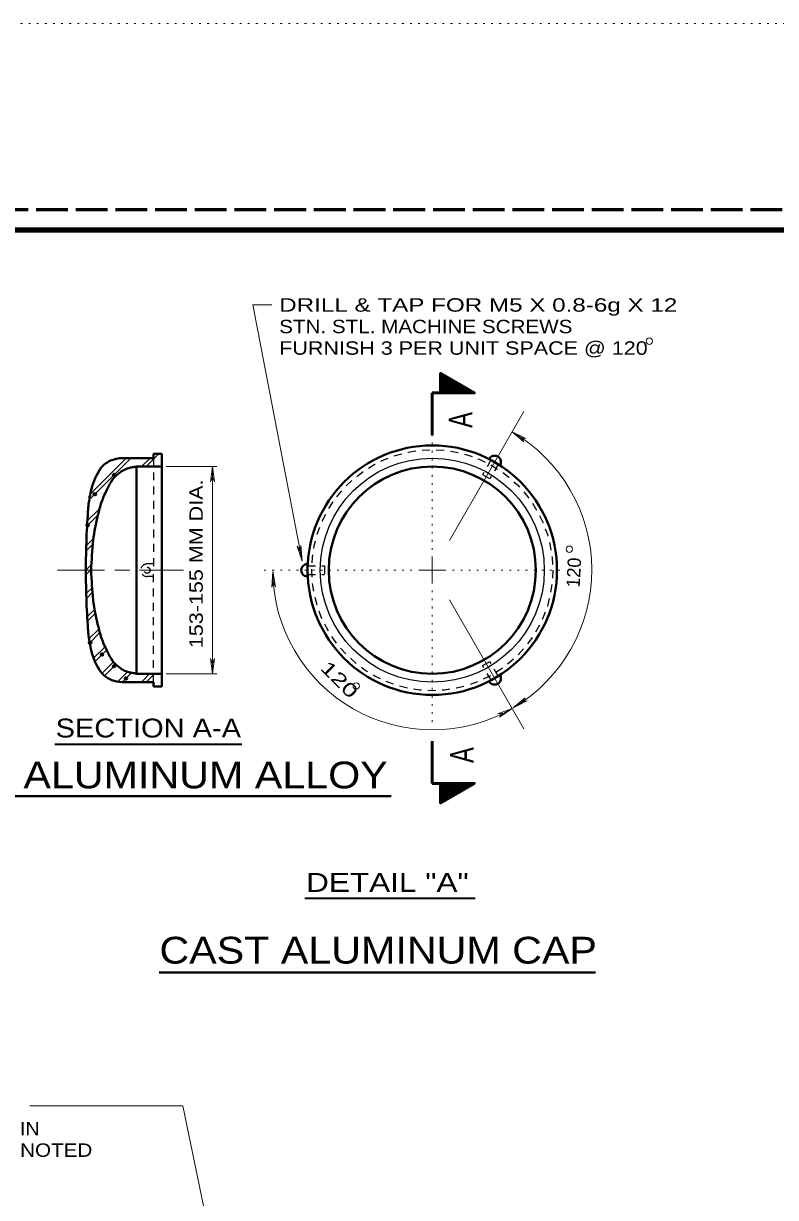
# Model space of a CAD drawing. Extents: x 312583 to 312854, y 144419 to 144597.
# Drawn here: x 312680.5 to 312723.1, y 144530.3 to 144596.8 of the extents above; entities that cross this region are included whole.
import ezdxf
from ezdxf.enums import TextEntityAlignment as Align

# ---------------------------------------------------------------- set-up
doc = ezdxf.new("R2010")
doc.units = 0
doc.header["$LTSCALE"] = 0.3
doc.header["$PDMODE"] = 32
doc.header["$PDSIZE"] = 0.15
for name, pattern in [('DOTTED', [1.5, 0.3, -1.2]), ('LONG_DASHED', [7.5, 6, -1.5]), ('SHORT_DASHED', [2.7, 1.5, -1.2])]:
    doc.linetypes.add(name, pattern=pattern)
for name, color, linetype, lineweight in [('1', 7, 'Continuous', 35), ('2', 7, 'Continuous', 13), ('62', 7, 'DOTTED', 13), ('63', 7, 'LONG_DASHED', 60)]:
    doc.layers.add(name, color=color, linetype=linetype, lineweight=lineweight)

msp = doc.modelspace()

# ---------------------------------------------------------------- linework, layer by layer
at = {"layer": '1', "lineweight": 13}
for p, q in [((312708.8486, 144574.7913), (312704.6319, 144567.485)), ((312684.2616, 144569.8463), (312686.5693, 144572.1616)), ((312684.2999, 144570.1606), (312686.2626, 144572.1233)), ((312687.1749, 144571.6786), (312687.6579, 144572.1616)), ((312687.4433, 144571.6786), (312688.1639, 144572.3993)), ((312687.8496, 144572.3533), (312687.8956, 144572.3993)), ((312684.0853, 144568.3206), (312684.7139, 144568.9493)), ((312684.0929, 144568.6043), (312684.7829, 144569.2866)), ((312684.0546, 144567.209), (312684.4379, 144567.5846)), ((312684.0469, 144566.9253), (312684.3919, 144567.2703)), ((312684.0163, 144565.8136), (312684.3306, 144566.128)), ((312684.0239, 144565.5453), (312684.3153, 144565.8443)), ((312684.0393, 144564.4796), (312684.3766, 144564.817)), ((312684.0469, 144564.2113), (312684.3996, 144564.564)), ((312708.8486, 144556.8283), (312704.6319, 144564.1346)), ((312684.0699, 144563.1533), (312684.5376, 144563.621)), ((312684.0853, 144562.8926), (312684.5759, 144563.391)), ((312684.1926, 144561.919), (312684.7293, 144562.4556)), ((312684.2156, 144561.6736), (312684.7983, 144562.2563)), ((312684.5069, 144560.884), (312685.1049, 144561.4743)), ((312684.5989, 144560.7), (312685.1816, 144561.2826)), ((312684.9516, 144559.9716), (312685.6109, 144560.631)), ((312685.0743, 144559.8183), (312685.7489, 144560.5006)), ((312685.8486, 144559.5116), (312686.4159, 144560.079)), ((312686.1093, 144559.504), (312686.6306, 144560.0176)), ((312687.1673, 144559.4733), (312687.6349, 144559.941)), ((312687.4356, 144559.4733), (312687.9033, 144559.941)), ((312688.2713, 144559.2203), (312688.3249, 144559.2816))]:
    msp.add_line(p, q, dxfattribs=at)
at = {"layer": '1', "lineweight": 40}
for p, q in [((312687.8496, 144572.1616), (312686.4083, 144572.1616)), ((312687.8496, 144572.1616), (312687.8496, 144572.3993)), ((312706.8859, 144572.108), (312707.5069, 144571.7553)), ((312686.8913, 144571.6786), (312686.8913, 144565.8136)), ((312688.3249, 144571.6786), (312688.3249, 144565.8136)), ((312696.5896, 144565.4533), (312696.5896, 144566.1663)), ((312686.8913, 144559.941), (312686.8913, 144565.8136)), ((312688.3249, 144559.941), (312688.3249, 144565.8136)), ((312687.8496, 144559.458), (312686.4083, 144559.458)), ((312687.8496, 144559.458), (312687.8496, 144559.2203)), ((312707.5069, 144559.872), (312706.8859, 144559.5116))]:
    msp.add_line(p, q, dxfattribs=at)
at = {"layer": '1', "linetype": 'SHORT_DASHED', "lineweight": 25}
for p, q in [((312687.8496, 144572.1616), (312687.8496, 144565.8136)), ((312706.9856, 144572.0543), (312706.5103, 144571.2186)), ((312707.3996, 144571.8166), (312706.9243, 144570.981)), ((312706.9243, 144570.981), (312706.5103, 144571.2186)), ((312687.8496, 144566.1663), (312687.4893, 144566.1663)), ((312687.8496, 144565.4533), (312687.4893, 144565.4533)), ((312687.8496, 144559.458), (312687.8496, 144565.8136)), ((312696.5896, 144566.0513), (312697.5479, 144566.0513)), ((312696.5896, 144565.5683), (312697.5479, 144565.5683)), ((312697.5479, 144566.0513), (312697.5479, 144565.5683)), ((312706.5103, 144560.401), (312706.9243, 144560.6386)), ((312706.9933, 144559.573), (312706.5103, 144560.401)), ((312707.3996, 144559.8106), (312706.9243, 144560.6386))]:
    msp.add_line(p, q, dxfattribs=at)
at = {"layer": '1', "lineweight": 158}
msp.add_lwpolyline([(312616.5, 144423.1446), (312616.5, 144585.0846), (312849, 144585.0846)], dxfattribs=at)
at = {"layer": '1', "lineweight": 40}
for points in [[(312686.8913, 144571.6786), (312688.3249, 144571.6786), (312688.3249, 144572.3993), (312687.8496, 144572.3993)], [(312686.8913, 144559.941), (312688.3249, 144559.941), (312688.3249, 144559.2203), (312687.8496, 144559.2203)]]:
    msp.add_lwpolyline(points, dxfattribs=at)
for radius in [7.0687, 5.8708]:
    msp.add_circle((312703.6602, 144565.8098), radius, dxfattribs=at)
at = {"layer": '1', "linetype": 'SHORT_DASHED', "lineweight": 25}
for centre, radius in [((312703.6602, 144565.8098), 6.8291), ((312687.4912, 144565.8079), 0.17)]:
    msp.add_circle(centre, radius, dxfattribs=at)
at = {"layer": '1', "lineweight": 25}
msp.add_circle((312703.6602, 144565.8098), 6.3499, dxfattribs=at)
at = {"layer": '1', "lineweight": 40}
for centre, start, end in [((312707.1952, 144571.9345), 329.52448, 150.47552), ((312696.5885, 144565.8088), 89.52448, 270.47552), ((312707.1968, 144559.6861), 209.52448, 30.47552)]:
    msp.add_arc(centre, 0.3575, start, end, dxfattribs=at)
at = {"layer": '1', "linetype": 'SHORT_DASHED', "lineweight": 25}
msp.add_arc((312687.4921, 144565.8069), 0.3575, 90.15361, 269.84639, dxfattribs=at)
at = {"layer": '1', "lineweight": 40}
for points in [[(312684.0163, 144565.8136), (312684.0393, 144567.1706), (312684.1236, 144568.9263), (312684.2003, 144569.7466), (312684.3843, 144570.5746), (312684.6219, 144571.1726), (312684.9439, 144571.6786), (312685.4959, 144572.0466), (312685.7566, 144572.1233), (312686.4083, 144572.1616)], [(312686.8913, 144571.6786), (312686.6613, 144571.6403), (312686.4466, 144571.5943), (312686.1246, 144571.464), (312685.8333, 144571.257), (312685.4499, 144570.82), (312685.2046, 144570.36), (312684.9056, 144569.6623), (312684.7063, 144568.934), (312684.5453, 144568.221), (312684.4379, 144567.508), (312684.3153, 144565.7983)], [(312684.0163, 144565.8136), (312684.0393, 144564.449), (312684.1236, 144562.6933), (312684.2003, 144561.8806), (312684.3843, 144561.045), (312684.6219, 144560.447), (312684.9439, 144559.9486), (312685.4959, 144559.5806), (312685.7566, 144559.504), (312686.4083, 144559.458)], [(312686.8913, 144559.941), (312686.6613, 144559.987), (312686.4466, 144560.0253), (312686.1246, 144560.1556), (312685.8333, 144560.3626), (312685.4499, 144560.7996), (312685.2046, 144561.2596), (312684.9056, 144561.9573), (312684.7063, 144562.6856), (312684.5453, 144563.3986), (312684.4379, 144564.1193), (312684.3153, 144565.7983)]]:
    msp.add_spline(points, degree=3, dxfattribs=at)
at = {"layer": '1'}
for p in [(312685.6109, 144571.2033), (312684.5299, 144570.1146), (312684.1236, 144568.359), (312684.2616, 144561.712), (312684.9363, 144561.0373), (312685.6109, 144560.3626), (312686.2933, 144559.6803)]:
    msp.add_point(p, dxfattribs=at)
at = {"layer": '2'}
for p, q in [((312694.5579, 144580.8403), (312693.4923, 144580.8403)), ((312696.2753, 144566.3273), (312693.4923, 144580.8403)), ((312708.1816, 144573.6413), (312708.8563, 144573.0816)), ((312708.1816, 144573.6413), (312708.9713, 144573.2656)), ((312708.8563, 144573.0816), (312708.6799, 144573.327)), ((312708.9713, 144573.2656), (312708.6799, 144573.327)), ((312688.5703, 144571.6786), (312691.4453, 144571.6786)), ((312691.1999, 144571.6786), (312691.0926, 144570.8123)), ((312691.1999, 144559.941), (312691.1999, 144571.6786)), ((312691.1999, 144571.6786), (312691.3073, 144570.8123)), ((312691.0926, 144570.8123), (312691.1999, 144571.0883)), ((312691.3073, 144570.8123), (312691.1999, 144571.0883)), ((312696.0069, 144567.163), (312696.1603, 144566.91)), ((312696.2753, 144566.3273), (312696.0069, 144567.163)), ((312696.2139, 144567.2013), (312696.1603, 144566.91)), ((312696.2753, 144566.3273), (312696.2139, 144567.2013)), ((312703.6583, 144565.8136), (312703.6583, 144566.5803)), ((312682.4139, 144565.8136), (312685.0666, 144565.8136)), ((312685.6569, 144565.8136), (312686.5079, 144565.8136)), ((312687.0676, 144565.8136), (312689.5516, 144565.8136)), ((312694.6193, 144565.7293), (312694.5656, 144564.8553)), ((312694.6193, 144565.7293), (312694.7726, 144564.8706)), ((312703.6583, 144565.8136), (312702.8916, 144565.8136)), ((312703.6583, 144565.8136), (312702.8916, 144565.8136)), ((312703.6583, 144565.8136), (312703.6583, 144565.047)), ((312703.6583, 144565.8136), (312704.4249, 144565.8136)), ((312694.5656, 144564.8553), (312694.6499, 144565.139)), ((312694.7726, 144564.8706), (312694.6499, 144565.139)), ((312691.0926, 144560.8073), (312691.1999, 144560.5313)), ((312691.1999, 144559.941), (312691.0926, 144560.8073)), ((312691.3073, 144560.8073), (312691.1999, 144560.5313)), ((312691.1999, 144559.941), (312691.3073, 144560.8073)), ((312688.5703, 144559.941), (312691.4453, 144559.941)), ((312708.2506, 144558.0166), (312708.9176, 144558.584)), ((312708.2506, 144558.0166), (312709.0326, 144558.4076)), ((312708.9176, 144558.584), (312708.7489, 144558.3463)), ((312709.0326, 144558.4076), (312708.7489, 144558.3463)), ((312708.1816, 144557.9783), (312707.3613, 144557.6716)), ((312707.3613, 144557.6716), (312707.6603, 144557.71)), ((312708.1816, 144557.9783), (312707.4609, 144557.4876)), ((312707.4609, 144557.4876), (312707.6603, 144557.71))]:
    msp.add_line(p, q, dxfattribs=at)
at = {"layer": '2', "lineweight": 35}
for p, q in [((312704.1336, 144576.938), (312704.1489, 144576.9533)), ((312704.1336, 144576.892), (312704.1719, 144576.9456)), ((312704.1336, 144576.8383), (312704.1873, 144576.9303)), ((312704.1336, 144576.7923), (312704.2103, 144576.915)), ((312704.1336, 144576.7386), (312704.2333, 144576.9073)), ((312704.1336, 144576.7003), (312704.2486, 144576.892)), ((312704.1336, 144576.6466), (312704.2716, 144576.8843)), ((312704.1336, 144576.6006), (312704.2946, 144576.869)), ((312704.1336, 144576.5546), (312704.3099, 144576.8613)), ((312704.1336, 144576.5086), (312704.3406, 144576.846)), ((312704.1336, 144576.455), (312704.3559, 144576.8383)), ((312704.1336, 144576.409), (312704.3789, 144576.823)), ((312704.1336, 144576.363), (312704.4019, 144576.8153)), ((312704.1336, 144576.3093), (312704.4173, 144576.8)), ((312704.1336, 144576.2633), (312704.4403, 144576.7923)), ((312704.1336, 144576.2173), (312704.4556, 144576.777)), ((312704.1336, 144576.1636), (312704.4786, 144576.7616)), ((312704.1336, 144576.1176), (312704.5016, 144576.754)), ((312704.1336, 144576.0716), (312704.5169, 144576.7386)), ((312704.1336, 144576.0256), (312704.5399, 144576.7233)), ((312704.1336, 144575.972), (312704.5629, 144576.7156)), ((312704.1336, 144575.9336), (312704.5783, 144576.7003)), ((312704.1336, 144575.88), (312704.6089, 144576.6926)), ((312704.1489, 144575.857), (312704.6243, 144576.6773)), ((312704.1796, 144575.857), (312704.6473, 144576.6696)), ((312704.2103, 144575.857), (312704.6703, 144576.6543)), ((312704.2333, 144575.857), (312704.6856, 144576.6466)), ((312704.2639, 144575.857), (312704.7086, 144576.6313)), ((312704.2869, 144575.8646), (312704.7316, 144576.6236)), ((312704.3176, 144575.8646), (312704.7469, 144576.6083)), ((312704.3406, 144575.857), (312704.7699, 144576.6006)), ((312704.3713, 144575.857), (312704.7929, 144576.5853)), ((312704.4019, 144575.857), (312704.8083, 144576.57)), ((312704.4249, 144575.857), (312704.8313, 144576.5623)), ((312704.4556, 144575.857), (312704.8543, 144576.547)), ((312704.4863, 144575.857), (312704.8773, 144576.5316)), ((312704.5093, 144575.857), (312704.8926, 144576.524)), ((312704.5399, 144575.8646), (312704.9156, 144576.5086)), ((312704.5706, 144575.857), (312704.9386, 144576.501)), ((312704.5936, 144575.857), (312704.9539, 144576.4856)), ((312704.6166, 144575.857), (312704.9769, 144576.478)), ((312704.6473, 144575.857), (312704.9999, 144576.4626)), ((312704.6779, 144575.857), (312705.0153, 144576.455)), ((312704.7086, 144575.857), (312705.0383, 144576.4396)), ((312704.7316, 144575.857), (312705.0613, 144576.432)), ((312704.7623, 144575.857), (312705.0766, 144576.4166)), ((312704.7853, 144575.8646), (312705.1073, 144576.409)), ((312704.8159, 144575.857), (312705.1226, 144576.3936)), ((312704.8389, 144575.857), (312705.1456, 144576.3783)), ((312704.8696, 144575.857), (312705.1686, 144576.3706)), ((312704.9003, 144575.857), (312705.1839, 144576.3553)), ((312704.9233, 144575.857), (312705.2069, 144576.3476)), ((312704.9539, 144575.857), (312705.2299, 144576.3323)), ((312704.9846, 144575.857), (312705.2453, 144576.3246)), ((312705.0076, 144575.857), (312705.2683, 144576.3093)), ((312705.0383, 144575.857), (312705.2913, 144576.3016)), ((312705.0689, 144575.857), (312705.3066, 144576.2863)), ((312705.0919, 144575.857), (312705.3296, 144576.2786)), ((312705.1149, 144575.857), (312705.3526, 144576.2633)), ((312705.1456, 144575.857), (312705.3756, 144576.2556)), ((312705.1763, 144575.857), (312705.3909, 144576.2403)), ((312705.2069, 144575.857), (312705.4139, 144576.225)), ((312705.2299, 144575.857), (312705.4369, 144576.2173)), ((312705.2606, 144575.857), (312705.4523, 144576.202)), ((312705.2836, 144575.857), (312705.4753, 144576.1866)), ((312705.3143, 144575.857), (312705.4983, 144576.179)), ((312705.3373, 144575.857), (312705.5136, 144576.1636)), ((312705.3679, 144575.857), (312705.5366, 144576.156)), ((312705.3986, 144575.857), (312705.5596, 144576.1406)), ((312705.4216, 144575.857), (312705.5749, 144576.133)), ((312705.4523, 144575.857), (312705.6056, 144576.1176)), ((312705.4753, 144575.857), (312705.6209, 144576.11)), ((312705.5059, 144575.857), (312705.6439, 144576.0946)), ((312705.5366, 144575.857), (312705.6669, 144576.087)), ((312705.5596, 144575.857), (312705.6823, 144576.0716)), ((312705.5903, 144575.857), (312705.7053, 144576.064)), ((312705.6133, 144575.857), (312705.7283, 144576.0486)), ((312705.6439, 144575.857), (312705.7436, 144576.0333)), ((312705.6746, 144575.857), (312705.7666, 144576.0256)), ((312705.7053, 144575.857), (312705.7896, 144576.0103)), ((312705.7283, 144575.857), (312705.8049, 144575.995)), ((312705.7589, 144575.857), (312705.8279, 144575.9873)), ((312705.7819, 144575.857), (312705.8509, 144575.972)), ((312705.8049, 144575.857), (312705.8739, 144575.9643)), ((312705.8356, 144575.857), (312705.8893, 144575.949)), ((312705.8663, 144575.857), (312705.9123, 144575.9413)), ((312705.8969, 144575.857), (312705.9353, 144575.926)), ((312705.9199, 144575.857), (312705.9506, 144575.9183)), ((312705.9506, 144575.857), (312705.9736, 144575.903)), ((312705.9736, 144575.857), (312705.9966, 144575.8953)), ((312706.0043, 144575.857), (312706.0119, 144575.88)), ((312706.0349, 144575.857), (312706.0349, 144575.8723)), ((312682.2567, 144555.948), (312692.8636, 144555.948)), ((312704.1336, 144553.7003), (312704.6089, 144552.8876)), ((312704.1336, 144553.6466), (312704.5783, 144552.88)), ((312704.1336, 144553.6083), (312704.5629, 144552.8646)), ((312704.1336, 144553.5546), (312704.5399, 144552.857)), ((312704.1336, 144553.5086), (312704.5169, 144552.8416)), ((312704.1489, 144553.7233), (312704.6243, 144552.903)), ((312704.1796, 144553.7233), (312704.6473, 144552.9106)), ((312704.2103, 144553.7233), (312704.6703, 144552.926)), ((312704.2333, 144553.7233), (312704.6856, 144552.9336)), ((312704.2639, 144553.7233), (312704.7086, 144552.949)), ((312704.2869, 144553.7156), (312704.7316, 144552.9566)), ((312704.3176, 144553.7156), (312704.7469, 144552.972)), ((312704.3406, 144553.7233), (312704.7699, 144552.9796)), ((312704.3713, 144553.7233), (312704.7929, 144552.995)), ((312704.4019, 144553.7233), (312704.8083, 144553.0103)), ((312704.4249, 144553.7233), (312704.8313, 144553.018)), ((312704.4556, 144553.7233), (312704.8543, 144553.0333)), ((312704.4863, 144553.7233), (312704.8773, 144553.0486)), ((312704.5093, 144553.7233), (312704.8926, 144553.0563)), ((312704.5399, 144553.7156), (312704.9156, 144553.0716)), ((312704.5706, 144553.7233), (312704.9386, 144553.0793)), ((312704.5936, 144553.7233), (312704.9539, 144553.0946)), ((312704.6166, 144553.7233), (312704.9769, 144553.1023)), ((312704.6473, 144553.7233), (312704.9999, 144553.1176)), ((312704.6779, 144553.7233), (312705.0153, 144553.1253)), ((312704.7086, 144553.7233), (312705.0383, 144553.1406)), ((312704.7316, 144553.7233), (312705.0613, 144553.1483)), ((312704.7623, 144553.7233), (312705.0766, 144553.1636)), ((312704.7853, 144553.7156), (312705.1073, 144553.1713)), ((312704.8159, 144553.7233), (312705.1226, 144553.1866)), ((312704.8389, 144553.7233), (312705.1456, 144553.202)), ((312704.8696, 144553.7233), (312705.1686, 144553.2096)), ((312704.9003, 144553.7233), (312705.1839, 144553.225)), ((312704.9233, 144553.7233), (312705.2069, 144553.2326)), ((312704.9539, 144553.7233), (312705.2299, 144553.248)), ((312704.9846, 144553.7233), (312705.2453, 144553.2556)), ((312705.0076, 144553.7233), (312705.2683, 144553.271)), ((312705.0383, 144553.7233), (312705.2913, 144553.2786)), ((312705.0689, 144553.7233), (312705.3066, 144553.294)), ((312705.0919, 144553.7233), (312705.3296, 144553.3016)), ((312705.1149, 144553.7233), (312705.3526, 144553.317)), ((312705.1456, 144553.7233), (312705.3756, 144553.3246)), ((312705.1763, 144553.7233), (312705.3909, 144553.34)), ((312705.2069, 144553.7233), (312705.4139, 144553.3553)), ((312705.2299, 144553.7233), (312705.4369, 144553.363)), ((312705.2606, 144553.7233), (312705.4523, 144553.3783)), ((312705.2836, 144553.7233), (312705.4753, 144553.3936)), ((312705.3143, 144553.7233), (312705.4983, 144553.4013)), ((312705.3373, 144553.7233), (312705.5136, 144553.4166)), ((312705.3679, 144553.7233), (312705.5366, 144553.4243)), ((312705.3986, 144553.7233), (312705.5596, 144553.4396)), ((312705.4216, 144553.7233), (312705.5749, 144553.4473)), ((312705.4523, 144553.7233), (312705.6056, 144553.4626)), ((312705.4753, 144553.7233), (312705.6209, 144553.4703)), ((312705.5059, 144553.7233), (312705.6439, 144553.4856)), ((312705.5366, 144553.7233), (312705.6669, 144553.4933)), ((312705.5596, 144553.7233), (312705.6823, 144553.5086)), ((312705.5903, 144553.7233), (312705.7053, 144553.5163)), ((312705.6133, 144553.7233), (312705.7283, 144553.5316)), ((312705.6439, 144553.7233), (312705.7436, 144553.547)), ((312705.6746, 144553.7233), (312705.7666, 144553.5546)), ((312705.7053, 144553.7233), (312705.7896, 144553.57)), ((312705.7283, 144553.7233), (312705.8049, 144553.5853)), ((312705.7589, 144553.7233), (312705.8279, 144553.593)), ((312705.7819, 144553.7233), (312705.8509, 144553.6083)), ((312705.8049, 144553.7233), (312705.8739, 144553.616)), ((312705.8356, 144553.7233), (312705.8893, 144553.6313)), ((312705.8663, 144553.7233), (312705.9123, 144553.639)), ((312705.8969, 144553.7233), (312705.9353, 144553.6543)), ((312705.9199, 144553.7233), (312705.9506, 144553.662)), ((312705.9506, 144553.7233), (312705.9736, 144553.6773)), ((312705.9736, 144553.7233), (312705.9966, 144553.685)), ((312706.0043, 144553.7233), (312706.0119, 144553.7003)), ((312706.0349, 144553.7233), (312706.0349, 144553.708)), ((312704.1336, 144553.4626), (312704.5016, 144552.8263)), ((312704.1336, 144553.4166), (312704.4786, 144552.8186)), ((312704.1336, 144553.363), (312704.4556, 144552.8033)), ((312704.1336, 144553.317), (312704.4403, 144552.788)), ((312704.1336, 144553.271), (312704.4173, 144552.7803)), ((312704.1336, 144553.2173), (312704.4019, 144552.765)), ((312704.1336, 144553.1713), (312704.3789, 144552.7573)), ((312704.1336, 144553.1253), (312704.3559, 144552.742)), ((312704.1336, 144553.0716), (312704.3406, 144552.7343)), ((312704.1336, 144553.0256), (312704.3099, 144552.719)), ((312704.1336, 144552.9796), (312704.2946, 144552.7113)), ((312704.1336, 144552.9336), (312704.2716, 144552.696)), ((312704.1336, 144552.88), (312704.2486, 144552.6883)), ((312704.1336, 144552.8416), (312704.2333, 144552.673)), ((312704.1336, 144552.788), (312704.2103, 144552.6653)), ((312704.1336, 144552.742), (312704.1873, 144552.65)), ((312704.1336, 144552.6883), (312704.1719, 144552.6346)), ((312704.1336, 144552.6423), (312704.1489, 144552.627)), ((312696.439, 144547.2277), (312706.0861, 144547.2277))]:
    msp.add_line(p, q, dxfattribs=at)
at = {"layer": '2', "lineweight": 53}
for p, q in [((312703.6583, 144573.465), (312703.6583, 144575.857)), ((312704.1336, 144575.857), (312703.6583, 144575.857)), ((312703.6583, 144556.1153), (312703.6583, 144553.7233)), ((312704.1336, 144553.7233), (312703.6583, 144553.7233))]:
    msp.add_line(p, q, dxfattribs=at)
at = {"layer": '2', "linetype": 'DOTTED'}
for p, q in [((312703.6583, 144566.9636), (312703.6583, 144574.6303)), ((312702.5083, 144565.8136), (312693.7989, 144565.8136)), ((312704.8083, 144565.8136), (312711.0413, 144565.8136)), ((312703.6583, 144564.6636), (312703.6583, 144557.112))]:
    msp.add_line(p, q, dxfattribs=at)
at = {"layer": '2', "lineweight": 40}
for p, q in [((312673.6269, 144553.0103), (312701.3363, 144553.0103)), ((312688.1836, 144543.0187), (312712.9165, 144543.0187))]:
    msp.add_line(p, q, dxfattribs=at)
at = {"layer": '2', "lineweight": 53}
for points in [[(312704.1336, 144575.857), (312704.1336, 144576.9686), (312706.0503, 144575.857)], [(312704.1336, 144553.7233), (312704.1336, 144552.6116), (312706.0503, 144553.7233)]]:
    msp.add_lwpolyline(points, close=True, dxfattribs=at)
at = {"layer": '2'}
msp.add_lwpolyline([(312680.8338, 144535.4536), (312689.5201, 144535.4536), (312692.1345, 144522.75)], dxfattribs=at)
for centre in [(312715.9652, 144578.7849), (312711.427, 144566.9974), (312699.3458, 144559.2433)]:
    msp.add_circle(centre, 0.1797, dxfattribs=at)
for start, end in [(300.50993, 59.99393), (180.50993, 299.99393)]:
    msp.add_arc((312703.6602, 144565.8098), 9.0451, start, end, dxfattribs=at)
at = {"layer": '62'}
msp.add_line((312601.2, 144596.7846), (312853.5, 144596.7846), dxfattribs=at)
at = {"layer": '63'}
msp.add_line((312851.75, 144586.2246), (312583.526, 144586.2246), dxfattribs=at)

# ---------------------------------------------------------------- texts
at = {"layer": '2'}
for s, width, p in [('DRILL & TAP FOR M5 X 0.8-6g X 12', 1.35, (312694.9796, 144580.456)), ('STN. STL. MACHINE SCREWS', 1.15, (312694.9796, 144579.236)), ('FURNISH 3 PER UNIT SPACE @ 120', 1.2, (312694.9796, 144578.016)), ('AS SHOWN ON POLE DRAWING IN', 1.1, (312662.8859, 144533.7899)), ('RELATION TO SHOE BASE, AS NOTED', 1.15, (312662.8859, 144532.5699))]:
    msp.add_text(s, height=0.76, dxfattribs=dict(at, width=width)).set_placement(p)
at = {"layer": '2', "width": 0.75}
for p in [(312705.9276, 144574.3236), (312706.0119, 144555.3333)]:
    msp.add_text('A', height=1.34, rotation=90, dxfattribs=at).set_placement(p, align=Align.CENTER)
at = {"layer": '2'}
for s, rotation, width, p in [('153-155 MM DIA.', 90, 1.2, (312690.6495, 144561.3909)), ('120', 315, 1.45, (312697.258, 144560.2148))]:
    msp.add_text(s, height=0.76, rotation=rotation, dxfattribs=dict(at, width=width)).set_placement(p)
msp.add_text('120', height=0.76, rotation=87, dxfattribs=at).set_placement((312712.0148, 144564.8072))
for s, height, width, p in [('SECTION A-A', 1.07, 1.15, (312687.5598, 144556.3298)), ('CAST ALUMINUM ALLOY', 1.52, 1.15, (312687.3641, 144553.4456)), ('DETAIL "A"', 1.07, 1.25, (312701.1133, 144547.5819)), ('CAST ALUMINUM CAP', 1.52, 1.15, (312700.592, 144543.5172))]:
    msp.add_text(s, height=height, dxfattribs=dict(at, width=width)).set_placement(p, align=Align.CENTER)

doc.saveas('drawing.dxf')
